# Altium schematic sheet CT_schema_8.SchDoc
size 254 x 245 mm
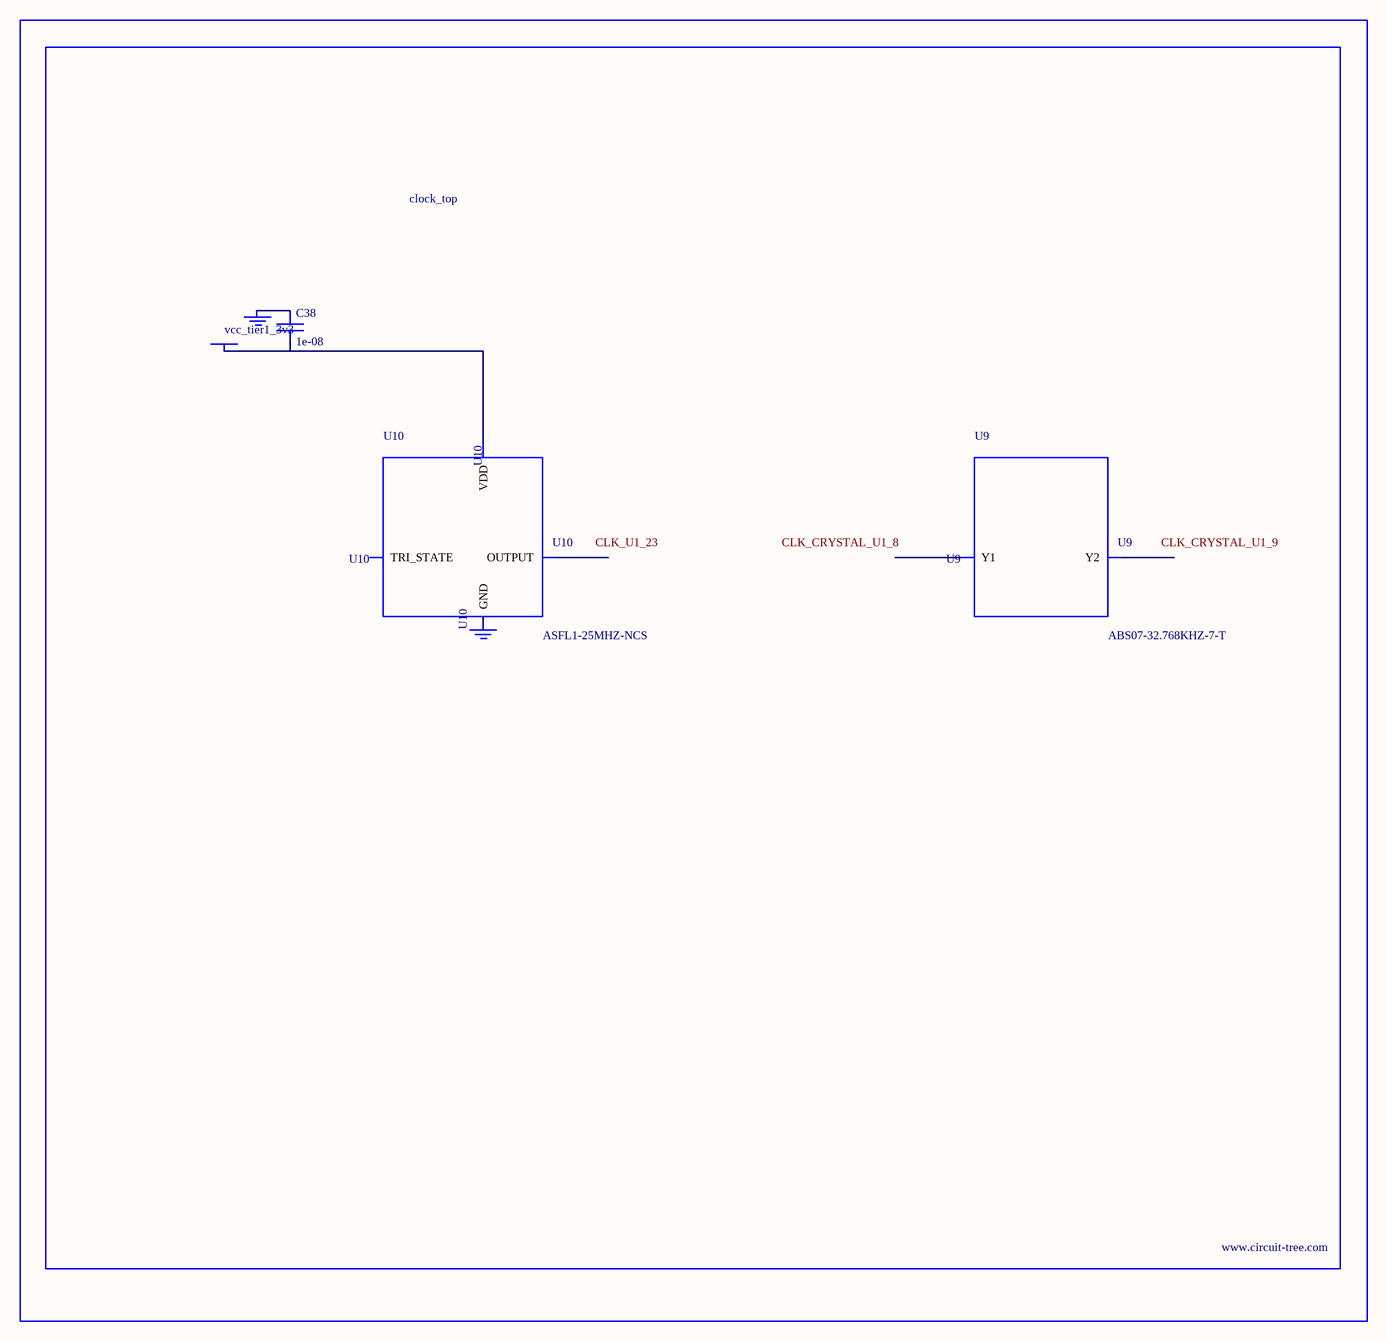
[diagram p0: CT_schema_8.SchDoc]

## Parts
BORDER7  (no value)
C38  1e-08  [C0402]
GND_INSTANCE_7_0  (no value)
GND_INSTANCE_7_1  (no value)
POWER_INSTANCE_7_0  vcc_tier1_3v3
U9  ABS07-32.768KHZ-7-T  [ABS07-32.768KHZ-7-T]
U10  ASFL1-25MHZ-NCS  [ASFL1]

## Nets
NetC38_1: C38.1 GND_INSTANCE_7_0.0(GND)
NetC38_2: C38.2 POWER_INSTANCE_7_0.0(PWR) U10.4(VDD)

Not connected (* = marked no-connect by the designer): GND_INSTANCE_7_1 0(GND); U9 1(Y1) 2(Y2); U10 1(TRI_STATE) 2(GND) 3(OUTPUT)

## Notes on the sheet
- Labels drawn without touching a wire or pin: CLK_CRYSTAL_U1_8, CLK_CRYSTAL_U1_9, CLK_U1_23

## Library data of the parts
BORDER7 = BORDER_PAGE7
C38 = C0402C103K3RAC
GND_INSTANCE_7_0 GND_INSTANCE_7_1 = GND
POWER_INSTANCE_7_0 = PWR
